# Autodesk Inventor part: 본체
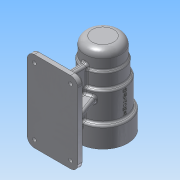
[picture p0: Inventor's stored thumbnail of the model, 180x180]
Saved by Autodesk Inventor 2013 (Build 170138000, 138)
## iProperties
Created: 2016-06
Part Number: 본체
Material: 알루미늄 6061
Document SubType Name: Modeling
Designer: Administrator
Density: 2.71 g/cm^3
Mass: 680.182 g
Surface Area: 650.644 cm^2
Volume: 250.99 cm^3
Author: Administrator
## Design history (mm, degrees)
sketch "스케치1"
  geometry: L1 (0, 0)-(0, -112); L2 (0, -112)-(34, -112); L3 (34, -112)-(34, -84); L4 (34, -84)-(30, -84); L5 (30, -84)-(30, -45); L6 (30, -45)-(27, -45); L7 (27, -45)-(27, -25); L8 (27, -25)-(25, -25); L9 (25, -25)-(25, 0); L10 (0, 0)-(25, 0)
  constraints: 20 end point, 6 parallel, 3 perpendicular, 1 vertical
  dimensions: "d0" = 112 distance of L1.start L1.end; "d1" = 50 diameter of L9 L1; "d2" = 54 diameter of L7 L1; "d3" = 60 diameter of L5 L1; "d4" = 68 diameter of L3 L1; "d5" = 25 distance between parallel lines of L8 L10; "d6" = 45 distance between parallel lines of L6 L10; "d7" = 84 distance between parallel lines of L4 L10
revolve "회전1" sketch "스케치1" stored, may be unused: angle "d8" = 90 deg
sketch "스케치2"
  geometry: C1 r 34 at (0, 0) reference; C2 r 21 at (0, 0)
  constraints: 1 centre point, 1 coincident
  dimensions: "d9" = 42 diameter of C2
extrude "돌출1" cut sketch "스케치2" distance "d10" = 15; taper "d11" = 0 deg
sketch "스케치3"
  geometry: C1 r 21 at (0, 0) reference; C2 r 24 at (0, 0)
  constraints: 1 centre point, 1 coincident
  dimensions: "d12" = 48 diameter of C2
extrude "돌출2" cut sketch "스케치3" distance "d13" = 54; taper "d14" = 0 deg
sketch "스케치4"
  geometry: C1 r 24 at (0, 0) reference; C2 r 21 at (0, 0)
  constraints: 1 centre point, 1 coincident
  dimensions: "d15" = 42 diameter of C2
extrude "돌출3" cut sketch "스케치4" distance "d16" = 12; taper "d17" = 0 deg
sketch "스케치5"
  geometry: L1 (-25, 0)-(25, 0) reference; L2 (25, 0)-(25, -25) reference; L3 (25, -25)-(27, -25) reference; L4 (27, -25)-(27, -45) reference; L5 (27, -45)-(30, -45) reference; L6 (30, -45)-(30, -84) reference; L7 (30, -84)-(34, -84) reference; L8 (34, -84)-(34, -112) reference; L9 (34, -112)-(21, -112) reference; L10 (21, -112)-(21, -97) reference; L11 (21, -97)-(24, -97) reference; L12 (24, -97)-(24, -43) reference; L13 (24, -43)-(21, -43) reference; L14 (21, -43)-(21, -31) reference; L15 (21, -31)-(-21, -31) reference; L16 (-21, -31)-(-21, -43) reference; L17 (-21, -43)-(-24, -43) reference; L18 (-24, -43)-(-24, -97) reference; L19 (-24, -97)-(-21, -97) reference; L20 (-21, -97)-(-21, -112) reference; L21 (-21, -112)-(-34, -112) reference; L22 (-34, -112)-(-34, -84) reference; L23 (-34, -84)-(-30, -84) reference; L24 (-30, -84)-(-30, -45) reference; L25 (-30, -45)-(-27, -45) reference; L26 (-27, -45)-(-27, -25) reference; L27 (-27, -25)-(-25, -25) reference; L28 (-25, -25)-(-25, 0) reference; L29 (0, -31)-(0, -13); L30 (0, -13)-(17.5, -13); L31 (17.5, -13)-(17.5, -31); 1 further point
  constraints: 6 end point, 2 perpendicular, 1 midpoint, 1 parallel, 1 point on line
  dimensions: "d18" = 18 distance of L29.start L29.end; "d19" = 35 diameter of L31 L29
revolve "회전2" sketch "스케치5" stored, may be unused: angle "d20" = 90 deg
sketch "스케치6"
  geometry: L1 (-25, 0)-(25, 0) reference; L2 (25, 0)-(25, -25) reference; L3 (25, -25)-(27, -25) reference; L4 (27, -25)-(27, -45) reference; L5 (27, -45)-(30, -45) reference; L6 (30, -45)-(30, -84) reference; L7 (30, -84)-(34, -84) reference; L8 (34, -84)-(34, -112) reference; L9 (34, -112)-(21, -112) reference; L10 (21, -112)-(21, -97) reference; L11 (21, -97)-(24, -97) reference; L12 (24, -97)-(24, -43) reference; L13 (24, -43)-(21, -43) reference; L14 (21, -43)-(21, -31) reference; L15 (21, -31)-(17.5, -31) reference; L16 (17.5, -31)-(17.5, -13) reference; L17 (17.5, -13)-(-17.5, -13) reference; L18 (-17.5, -13)-(-17.5, -31) reference; L19 (-17.5, -31)-(-21, -31) reference; L20 (-21, -31)-(-21, -43) reference; L21 (-21, -43)-(-24, -43) reference; L22 (-24, -43)-(-24, -97) reference; L23 (-24, -97)-(-21, -97) reference; L24 (-21, -97)-(-21, -112) reference; L25 (-21, -112)-(-34, -112) reference; L26 (-34, -112)-(-34, -84) reference; L27 (-34, -84)-(-30, -84) reference; L28 (-30, -84)-(-30, -45) reference; L29 (-30, -45)-(-27, -45) reference; L30 (-27, -45)-(-27, -25) reference; L31 (-27, -25)-(-25, -25) reference; L32 (-25, -25)-(-25, 0) reference; L33 (0, -13)-(0, -9); L34 (0, -9)-(16, -9); L35 (16, -9)-(16, -13); 1 further point
  constraints: 6 end point, 2 perpendicular, 1 midpoint, 1 parallel, 1 point on line
  dimensions: "d21" = 4 distance of L33.start L33.end; "d22" = 32 diameter of L35 L33
revolve "회전3" sketch "스케치6" stored, may be unused: angle "d23" = 90 deg
sketch "스케치7"
  geometry: L1 (-25, 0)-(25, 0) reference; L2 (25, 0)-(25, -25) reference; L3 (25, -25)-(27, -25) reference; L4 (27, -25)-(27, -45) reference; L5 (27, -45)-(30, -45) reference; L6 (30, -45)-(30, -84) reference; L7 (30, -84)-(34, -84) reference; L8 (34, -84)-(34, -112) reference; L9 (34, -112)-(21, -112) reference; L10 (21, -112)-(21, -97) reference; L11 (21, -97)-(24, -97) reference; L12 (24, -97)-(24, -43) reference; L13 (24, -43)-(21, -43) reference; L14 (21, -43)-(21, -31) reference; L15 (21, -31)-(17.5, -31) reference; L16 (17.5, -31)-(17.5, -13) reference; L17 (17.5, -13)-(16, -13) reference; L18 (16, -13)-(16, -9) reference; L19 (16, -9)-(-16, -9) reference; L20 (-16, -9)-(-16, -13) reference; L21 (-16, -13)-(-17.5, -13) reference; L22 (-17.5, -13)-(-17.5, -31) reference; L23 (-17.5, -31)-(-21, -31) reference; L24 (-21, -31)-(-21, -43) reference; L25 (-21, -43)-(-24, -43) reference; L26 (-24, -43)-(-24, -97) reference; L27 (-24, -97)-(-21, -97) reference; L28 (-21, -97)-(-21, -112) reference; L29 (-21, -112)-(-34, -112) reference; L30 (-34, -112)-(-34, -84) reference; L31 (-34, -84)-(-30, -84) reference; L32 (-30, -84)-(-30, -45) reference; L33 (-30, -45)-(-27, -45) reference; L34 (-27, -45)-(-27, -25) reference; L35 (-27, -25)-(-25, -25) reference; L36 (-25, -25)-(-25, 0) reference; L37 (0, -9)-(0, -6); L38 (0, -6)-(10.5, -6); L39 (10.5, -6)-(10.5, -9); 1 further point
  constraints: 6 end point, 2 perpendicular, 1 midpoint, 1 parallel, 1 point on line
  dimensions: "d24" = 3 distance of L37.start L37.end; "d25" = 21 diameter of L39 L37
revolve "회전4" sketch "스케치7" stored, may be unused: angle "d26" = 90 deg
node "작업 평면1"
sketch "스케치8"
  geometry: L1 (35, 0)-(-35, 0); L2 (-35, 0)-(-35, -112); L3 (-35, -112)-(35, -112); L4 (35, -112)-(35, 0); L5 (-34, -112)-(34, -112) reference; L6 (-25, 0)-(25, 0) reference; L7 (30, -45)-(30, -84) reference; L8 (34, -84)-(34, -112) reference; L9 (27, -25)-(27, -45) reference; L10 (25, 0)-(25, -25) reference; 2 further points
  constraints: 8 end point, 2 midpoint, 2 parallel, 1 horizontal, 1 perpendicular
  dimensions: "d28" = 70 distance of L3.end L2.end; "d29" = 112 distance of L2.end L1.end; "d30" = 35 distance from line of point (0, -112) L4
extrude "돌출4" join sketch "스케치8" distance "d31" = 10; taper "d32" = 0 deg
sketch "스케치9"
  geometry: L1 (-35, 0)-(35, 0) reference; L2 (35, 0)-(35, 112) reference; L3 (4, 92)-(-4, 92); L4 (-4, 92)-(-4, 20); L5 (-4, 20)-(4, 20); L6 (4, 20)-(4, 92); 5 further points
  constraints: 8 end point, 4 midpoint, 2 parallel, 1 horizontal, 1 horizontal alignment, 1 perpendicular, 1 vertical alignment
  dimensions: "d33" = 8 distance of L5.end L4.end; "d34" = 72 distance of L4.end L3.end
extrude "돌출5" join sketch "스케치9" stored distance "d35" = 10; taper "d36" = 0 deg
node "작업 평면2"
sketch "스케치10"
  geometry: L1 (0, 10)-(0, 0) reference; L2 (0, 0)-(-70, 0) reference; L3 (-70, 0)-(-70, 10) reference; L4 (-70, 10)-(-39, 10) reference; L5 (-39, 10)-(-39, 40.268) reference; L6 (-31, 40.268)-(-31, 10) reference; L7 (-31, 10)-(0, 10) reference; L8 (-50.509, 44.32)-(-63, 10); C1 r 24 at (-35, 70) reference; A1 r 30 centre (-35, 70) between (-31, 40.268) and (-39, 40.268) reference; 1 further point
  constraints: 2 end point, 1 point on circle, 1 point on line
  dimensions: "d37" = 7 distance from line of L3 L8.end; "d38" = 110 deg angle of L4 L8
feature "리브1" sketch "스케치10" dims "d39" = 1, "d40" = 8, "d41" = 0, "d42" = 0, "d43" = 1, "d44" = 1
fillet "모깎기1" dims "d45" = 3
fillet "모깎기2" dims "d46" = 3
fillet "모깎기3" dims "d47" = 3
fillet "모깎기4" dims "d48" = 10
fillet "모깎기5" dims "d49" = 10
chamfer "모따기1" distance "d51" = 1; stored, may be unused: second distance "d52" = 2, angle "d53" = 45 deg
fillet "모깎기7" dims "d54" = 0.3
fillet "모깎기8" dims "d55" = 3
fillet "모깎기9" dims "d56" = 3
sketch "스케치11"
  geometry: L1 (0, 0)-(0, 26); C1 r 22 at (0, 0) reference; 1 further point
  constraints: 2 end point, 1 coincident, 1 vertical
  dimensions: "d57" = 26 distance of L1.start L1.end
hole "구멍1" sketch "스케치11" at (0, 26) diameter "d58" = 3.242; stored, may be unused: countersink angle "d62" = 90 deg, drill point angle "d64" = 118 deg; dims "d59" = 8, "d60" = 4, "d61" = 2, "d63" = 11
sketch "스케치12"
  geometry: A1 r 7 centre (-25, 10) between (-32, 10) and (-25, 3) reference; A2 r 7 centre (25, 10) between (25, 3) and (32, 10) reference; A3 r 7 centre (25, 102) between (32, 102) and (25, 109) reference; A4 r 7 centre (-25, 102) between (-25, 109) and (-32, 102) reference; 5 further points
  constraints: 4 coincident
hole "구멍2" sketch "스케치12" at (-25, 102), (25, 102), (25, 10), (-25, 10) diameter "d68" = 5; stored, may be unused: countersink angle "d72" = 90 deg, drill point angle "d74" = 118 deg; dims "d69" = 5, "d70" = 9, "d71" = 4, "d73" = 11
fillet "모깎기10" dims "d75" = 3
fillet "모깎기11" dims "d76" = 3
node "작업 평면3"
sketch "스케치13"
  geometry: L1 (-60, -58.061)-(-60, -110.66) reference; L2 (-60, -110.66)-(-70, -110.66) reference; L3 (-70, -110.66)-(-70, -1.34) reference; L4 (-70, -1.34)-(-60, -1.34) reference; L5 (-60, -1.34)-(-60, -53.939) reference; L6 (-59.998, -55)-(-59.998, -57) reference; L7 (0, -47.196)-(0, -81) reference; L8 (-16, -112)-(-16, -86.657) reference; L9 (16, -112)-(-16, -112) reference; L10 (16, -86.657)-(16, -112) reference; 5 further points
  constraints: 1 midpoint, 1 vertical alignment, 7 other
  dimensions: "d78" = 48 distance of point (0, -112) point (0, -64)
feature "엠보싱1" sketch "스케치13" dims "d80" = 0.5, "d81" = 0
chamfer "모따기2" distance "d82" = 4; stored, may be unused: second distance "d83" = 2, angle "d84" = 45 deg
node "솔리드1"
mirror "대칭1"
pattern_circular "원형 패턴1" dims angle "d66" = 360 deg
node "절단 모서리 투영1"
node "절단 모서리 투영2"
node "절단 모서리 투영3"
node "절단 모서리 투영4"
node "절단 모서리 투영5"
